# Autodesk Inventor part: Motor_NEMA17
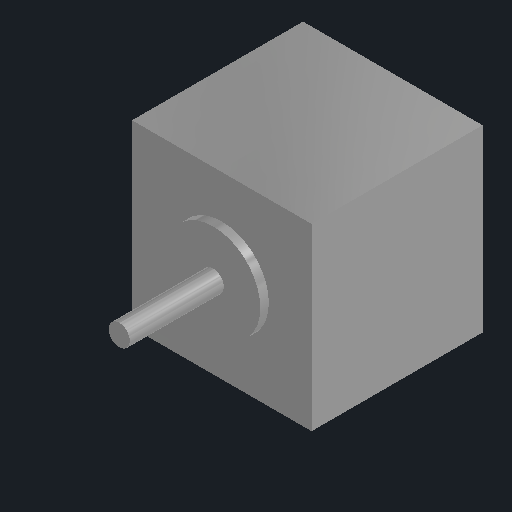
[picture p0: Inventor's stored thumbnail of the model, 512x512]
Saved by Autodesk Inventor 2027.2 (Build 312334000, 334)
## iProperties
Part Number: Motor_NEMA17
Material: Genérico
Document SubType Name: Modelado
Designer: Usuario
Appearance: Por defecto
Author: Usuario
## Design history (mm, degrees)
sketch "Boceto1"
  geometry: L1 (-21, -21)-(21, -21); L2 (21, -21)-(21, 21); L3 (21, 21)-(-21, 21); L4 (-21, 21)-(-21, -21)
  constraints: 8 end point, 2 parallel, 1 horizontal, 1 perpendicular
extrude "Extrusión1" new body sketch "Boceto1" distance "d0" = 40; taper "d1" = 0 deg
sketch "Boceto2"
  geometry: C1 r 11 at (0, 0)
  constraints: 1 centre point
extrude "Extrusión2" join sketch "Boceto2" distance "d2" = 2; taper "d3" = 0 deg
sketch "Boceto3"
  geometry: C1 r 2.5 at (0, 0)
  constraints: 1 centre point
extrude "Extrusión3" join sketch "Boceto3" distance "d4" = 24; taper "d5" = 0 deg
node "Sólido1"
node "Cuerpos sólidos"
node "Cuerpos de superficie"
